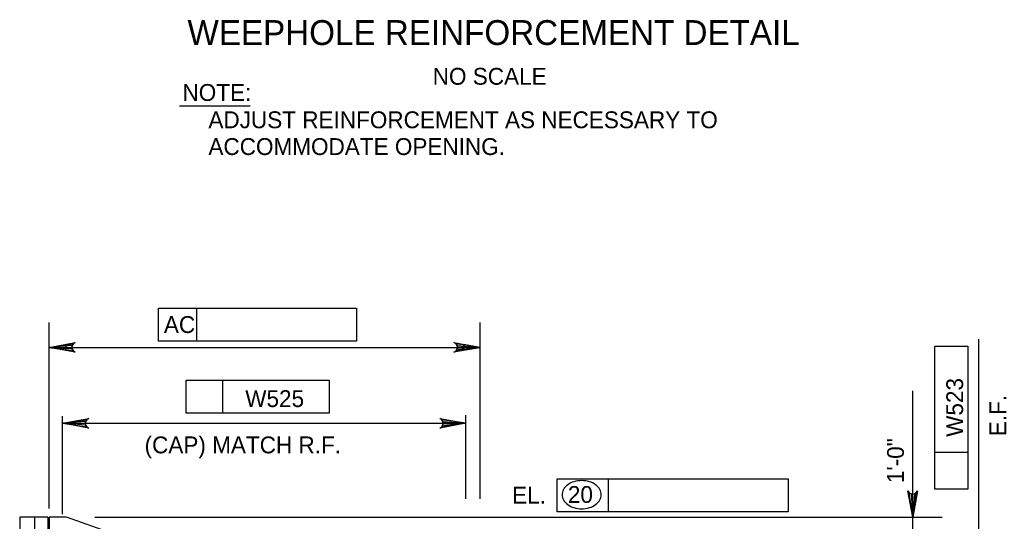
# Model space of a CAD drawing. Extents: x 638255 to 640306, y 296059 to 298435.
# Drawn here: x 639660.4 to 639836.1, y 297426.9 to 297516.1 of the extents above; entities that cross this region are included whole.
import ezdxf

# ---------------------------------------------------------------- set-up
doc = ezdxf.new("R2010")
doc.units = 0
doc.layers.add('Level 10', color=7, linetype='Continuous')
doc.layers.add('Level 4', color=7, linetype='Continuous')

msp = doc.modelspace()

# ---------------------------------------------------------------- linework, layer by layer
at = {"layer": 'Level 10'}
for p, q in [((639665.37, 297427.61), (639660.37, 297427.61)), ((639660.37, 297427.61), (639660.37, 297406.39)), ((639663.03, 297427.61), (639663.03, 297339.5)), ((639665.37, 297427.61), (639665.37, 297339.5)), ((639665.62, 297427.61), (639665.62, 297339.5)), ((639668.69, 297427.61), (639665.62, 297427.61)), ((639742.37, 297401.52), (639668.69, 297427.61))]:
    msp.add_line(p, q, dxfattribs=at)
at = {"layer": 'Level 4'}
for p, q in [((639688.82, 297500.79), (639701.41, 297500.79)), ((639685.11, 297464.8), (639720.34, 297464.8)), ((639685.11, 297458.9), (639685.11, 297464.8)), ((639691.94, 297458.9), (639691.94, 297464.8)), ((639720.34, 297464.8), (639720.34, 297458.9)), ((639665.62, 297429.15), (639665.62, 297462.24)), ((639742.37, 297430.84), (639742.37, 297462.24)), ((639720.34, 297458.9), (639685.11, 297458.9)), ((639831.22, 297429.82), (639831.22, 297459.28)), ((639668.57, 297457.82), (639739.42, 297457.82)), ((639823.34, 297432.56), (639823.34, 297458.04)), ((639823.34, 297458.04), (639829.24, 297458.04)), ((639829.24, 297458.04), (639829.24, 297432.56)), ((639689.99, 297452), (639715.48, 297452)), ((639689.99, 297446.11), (639689.99, 297452)), ((639696.57, 297446.11), (639696.57, 297452)), ((639715.48, 297452), (639715.48, 297446.11)), ((639819.43, 297413.94), (639819.43, 297450.1)), ((639715.48, 297446.11), (639689.99, 297446.11)), ((639668.01, 297428.12), (639668.01, 297445.56)), ((639668.01, 297444.31), (639739.84, 297444.31)), ((639739.84, 297430.84), (639739.84, 297445.76)), ((639829.24, 297439.13), (639823.34, 297439.13)), ((639756.09, 297434.43), (639797.22, 297434.43)), ((639756.09, 297428.54), (639756.09, 297434.43)), ((639765.24, 297428.54), (639765.24, 297434.43)), ((639797.22, 297434.43), (639797.22, 297428.54)), ((639829.24, 297432.56), (639823.34, 297432.56)), ((639797.22, 297428.54), (639756.09, 297428.54)), ((639831.22, 297422.16), (639831.22, 297429.82)), ((639673.74, 297427.61), (639824.7, 297427.61))]:
    msp.add_line(p, q, dxfattribs=at)
for points in [[(639665.62, 297457.82), (639670.27, 297458.69), (639669.92, 297458.44), (639669.73, 297458.13), (639669.68, 297457.82), (639669.73, 297457.51), (639669.92, 297457.19), (639670.27, 297456.95), (639665.62, 297457.82), (639669.92, 297457.19), (639669.73, 297457.51), (639665.62, 297457.82), (639669.68, 297457.82), (639669.73, 297458.13), (639665.62, 297457.82), (639669.92, 297458.44)], [(639742.37, 297457.82), (639737.72, 297456.95), (639738.08, 297457.19), (639738.26, 297457.51), (639738.32, 297457.82), (639738.26, 297458.13), (639738.08, 297458.44), (639737.72, 297458.69), (639742.37, 297457.82), (639738.08, 297458.44), (639738.26, 297458.13), (639742.37, 297457.82), (639738.32, 297457.82), (639738.26, 297457.51), (639742.37, 297457.82), (639738.08, 297457.19)], [(639668.01, 297444.31), (639672.66, 297445.18), (639672.3, 297444.94), (639672.11, 297444.62), (639672.06, 297444.31), (639672.11, 297444), (639672.3, 297443.69), (639672.66, 297443.44), (639668.01, 297444.31), (639672.3, 297443.69), (639672.11, 297444), (639668.01, 297444.31), (639672.06, 297444.31), (639672.11, 297444.62), (639668.01, 297444.31), (639672.3, 297444.94)], [(639739.84, 297444.31), (639735.19, 297443.44), (639735.55, 297443.69), (639735.74, 297444), (639735.79, 297444.31), (639735.74, 297444.62), (639735.55, 297444.94), (639735.19, 297445.18), (639739.84, 297444.31), (639735.55, 297444.94), (639735.74, 297444.62), (639739.84, 297444.31), (639735.79, 297444.31), (639735.74, 297444), (639739.84, 297444.31), (639735.55, 297443.69)], [(639819.43, 297427.61), (639818.56, 297432.26), (639818.81, 297431.9), (639819.12, 297431.72), (639819.43, 297431.67), (639819.75, 297431.72), (639820.06, 297431.9), (639820.3, 297432.26), (639819.43, 297427.61), (639820.06, 297431.9), (639819.75, 297431.72), (639819.43, 297427.61), (639819.43, 297431.67), (639819.12, 297431.72), (639819.43, 297427.61), (639818.81, 297431.9)]]:
    msp.add_lwpolyline(points, dxfattribs=at)
for points in [[(639668.57, 297458.31), (639668.57, 297457.33), (639665.62, 297457.82)], [(639739.42, 297458.31), (639739.42, 297457.33), (639742.37, 297457.82)]]:
    msp.add_lwpolyline(points, close=True, dxfattribs=at)
for centre, radius, start, end in [((639760.11, 297430.4), 3.65, 106.5358, 125.6316), ((639760.46, 297429.24), 4.86, 90, 106.5358), ((639760.46, 297429.24), 4.86, 73.4642, 90), ((639760.8, 297430.4), 3.65, 54.3684, 73.4642), ((639758.78, 297431.59), 1.82, 149.9767, 180), ((639759.59, 297431.13), 2.75, 125.6316, 149.9767), ((639761.33, 297431.13), 2.75, 30.0233, 54.3684), ((639762.13, 297431.59), 1.82, 0, 30.0233), ((639758.78, 297431.59), 1.82, 180, 210.0233), ((639759.59, 297432.06), 2.75, 210.0233, 234.3684), ((639761.33, 297432.06), 2.75, 305.6316, 329.9767), ((639762.13, 297431.59), 1.82, 329.9767, 0), ((639760.11, 297432.79), 3.65, 234.3684, 253.4642), ((639760.46, 297433.95), 4.86, 253.4642, 270), ((639760.46, 297433.95), 4.86, 270, 286.5358), ((639760.8, 297432.79), 3.65, 286.5358, 305.6316)]:
    msp.add_arc(centre, radius, start, end, dxfattribs=at)

# ---------------------------------------------------------------- texts
for s, height, p in [('WEEPHOLE REINFORCEMENT DETAIL', 4.4207, (639690.25, 297511.65)), ('NO SCALE', 3, (639733.93, 297504.57)), ('NOTE:', 3, (639689.36, 297501.69)), ('ADJUST REINFORCEMENT AS NECESSARY TO', 3.0001, (639693.98, 297496.83)), ('ACCOMMODATE OPENING.', 3.0001, (639693.98, 297492.06)), ('AC', 3, (639686.05, 297460.38)), ('W525', 3, (639700.54, 297447.2)), ('(CAP) MATCH R.F.', 3.0001, (639682.61, 297438.96)), ('EL.', 3, (639748.08, 297430.02)), ('20', 3, (639758, 297430.13))]:
    msp.add_text(s, height=height, dxfattribs=at).set_placement(p)
for s, p in [('W523', (639828.4, 297441.89)), ('E.F.', (639836.09, 297442.02)), ('1\'-0"', (639817.86, 297433.65))]:
    msp.add_text(s, height=3, rotation=90, dxfattribs=at).set_placement(p)

doc.saveas('drawing.dxf')
